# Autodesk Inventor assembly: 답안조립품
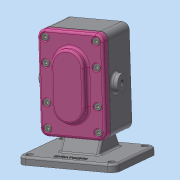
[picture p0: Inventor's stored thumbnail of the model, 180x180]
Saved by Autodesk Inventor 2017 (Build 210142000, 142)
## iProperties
Part Number: 답안조립품
Material: 일반
Document SubType Name: Assembly
Designer: MRC
Author: MRC
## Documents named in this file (11)
- C:\Users\MRC\Desktop\700407V1044\답안조립품.iam
- C:\Users\MRC\Desktop\700407V1044\본체.ipt
- C:\Users\MRC\Desktop\700407V1044\개스킷.ipt
- C:\Users\MRC\Desktop\700407V1044\메인축.ipt
- C:\Users\MRC\Desktop\700407V1044\베어링부시.ipt
- C:\Users\MRC\Desktop\700407V1044\볼트 M5.ipt
- C:\Users\MRC\Desktop\700407V1044\서브축.ipt
- C:\Users\MRC\Desktop\700407V1044\스퍼기어.ipt
- C:\Users\MRC\Desktop\700407V1044\오일 실 16 28 7.ipt
- C:\Users\MRC\Desktop\700407V1044\커버.ipt
- C:\Users\MRC\Desktop\700407V1044\키 6 x 6 x 18.ipt
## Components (1 placed, 1 different names)
1. 개스킷:1
